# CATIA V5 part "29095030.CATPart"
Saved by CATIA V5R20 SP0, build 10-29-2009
Part number: 29095030
Definition: NONE
Nomenclature: 29095030
Source: Unknown
Description: 29095030
Bounding box of the stored display mesh (mm): x -15 to 44.548, y -61.5 to 96.048, z -51.5 to 51.5
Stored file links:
  C:\Users\Utente\Desktop\IO LAVORO\3D X SITO CF\X SITO\PLASTICA\RF1\29095030.CATPart
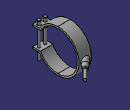
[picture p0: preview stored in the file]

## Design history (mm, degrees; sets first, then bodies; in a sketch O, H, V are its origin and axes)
Body1 "29095030" (main body)
  Solid1: solid without history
